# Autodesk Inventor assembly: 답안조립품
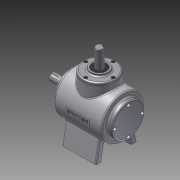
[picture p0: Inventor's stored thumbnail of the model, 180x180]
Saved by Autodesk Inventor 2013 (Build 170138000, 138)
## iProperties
Created: 2015-01
Part Number: 답안조립품
Document SubType Name: Assembly
Designer: Administrator
Author: Administrator
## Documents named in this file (15)
- C:\Documents and Settings\Administrator\바탕 화면\450106V1025\답안조립품.iam
- C:\Documents and Settings\Administrator\바탕 화면\450106V1025\본체.ipt
- C:\Documents and Settings\Administrator\바탕 화면\450106V1025\메인 베벨기어.ipt
- C:\Documents and Settings\Administrator\바탕 화면\450106V1025\메인 축.ipt
- 메인 축.ipt
- C:\Documents and Settings\Administrator\바탕 화면\450106V1025\베어링 6203.ipt
- C:\Documents and Settings\Administrator\바탕 화면\450106V1025\서브 베벨기어.ipt
- C:\Documents and Settings\Administrator\바탕 화면\450106V1025\서브 축.ipt
- 서브 축.ipt
- C:\Documents and Settings\Administrator\바탕 화면\450106V1025\오일실.ipt
- C:\Documents and Settings\Administrator\바탕 화면\450106V1025\커버2.ipt
- C:\Documents and Settings\Administrator\바탕 화면\450106V1025\커버.ipt
- C:\Documents and Settings\Administrator\바탕 화면\450106V1025\키 4x4.ipt
- C:\Documents and Settings\Administrator\바탕 화면\450106V1025\키 5x5.ipt
- C:\Documents and Settings\Administrator\바탕 화면\450106V1025\M4.ipt
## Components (8 placed, 1 different names)
1. M4:1
2. M4:3
3. M4:4
4. M4:5
5. M4:2
6. M4:6
7. M4:7
8. M4:8
